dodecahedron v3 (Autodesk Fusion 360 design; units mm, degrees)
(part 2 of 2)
sketch "Sketch12" plane through (4.7433, 19.8444, -10.2039) normal (0.2079, 0.8699, -0.4473) x axis (-0.9726, 0.2325, 0)
  line L1 (-17.4918, 12.7643) -> (-28.5055, 46.2674)
  line L2 (17.775, 12.8859) -> (-17.4918, 12.7643)
  line L3 (28.5573, 46.4642) -> (17.775, 12.8859)
  line L4 (-0.0456, 67.0951) -> (28.5573, 46.4642)
  line L5 (-28.5055, 46.2674) -> (-0.0456, 67.0951)
  line L6 (-30.2958, 66.0429) -> (-30.2958, 36.2773)
  line L7 (-0.5302, 66.0429) -> (-30.2958, 66.0429)
  line L8 (29.2354, 66.0429) -> (-0.5302, 66.0429)
  line L9 (29.2354, 36.2773) -> (29.2354, 66.0429)
  line L10 (29.2354, 6.5116) -> (29.2354, 36.2773)
  line L11 (-0.5302, 6.5116) -> (29.2354, 6.5116)
  line L12 (-30.2958, 6.5116) -> (-0.5302, 6.5116)
  line L13 (-30.2958, 36.2773) -> (-30.2958, 6.5116)
  curve K1 (2.3724, 16.2406) -> (1.4713, 16.1226)
  curve K2 (1.9297, 17.1948) -> (2.3724, 16.2406)
  curve K3 (1.5053, 19.8254) -> (1.9297, 17.1948)
  curve K4 (2.1828, 21.6353) -> (1.5053, 19.8254)
  curve K5 (2.1525, 23.8138) -> (2.1828, 21.6353)
  curve K6 (1.4481, 26.0743) -> (2.1525, 23.8138)
  curve K7 (2.1376, 26.8386) -> (1.4481, 26.0743)
  curve K8 (2.842, 25.6825) -> (2.1376, 26.8386)
  curve K9 (4.016, 24.576) -> (2.842, 25.6825)
  curve K10 (5.1901, 24.2437) -> (4.016, 24.576)
  curve K11 (2.9753, 28.5266) -> (5.1901, 24.2437)
  curve K12 (1.9028, 32.4009) -> (2.9753, 28.5266)
  curve K13 (2.3455, 34.8221) -> (1.9028, 32.4009)
  curve K14 (7.0685, 30.1247) -> (2.3455, 34.8221)
  curve K15 (9.4636, 26.5383) -> (7.0685, 30.1247)
  curve K16 (9.0345, 29.9776) -> (9.4636, 26.5383)
  curve K17 (9.4117, 31.0677) -> (9.0345, 29.9776)
  curve K18 (11.0674, 29.1728) -> (9.4117, 31.0677)
  curve K19 (12.8737, 28.4823) -> (11.0674, 29.1728)
  curve K20 (13.0657, 29.1867) -> (12.8737, 28.4823)
  curve K21 (14.1127, 28.4823) -> (13.0657, 29.1867)
  curve K22 (15.3543, 27.7778) -> (14.1127, 28.4823)
  curve K23 (16.5462, 26.6038) -> (15.3543, 27.7778)
  curve K24 (17.8696, 26.1998) -> (16.5462, 26.6038)
  curve K25 (18.6915, 27.5937) -> (17.8696, 26.1998)
  curve K26 (18.3393, 28.2472) -> (18.6915, 27.5937)
  curve K27 (15.3117, 29.4154) -> (18.3393, 28.2472)
  curve K28 (14.2524, 30.8588) -> (15.3117, 29.4154)
  curve K29 (13.1149, 32.0044) -> (14.2524, 30.8588)
  curve K30 (10.4098, 33.4565) -> (13.1149, 32.0044)
  curve K31 (12.0271, 33.8756) -> (10.4098, 33.4565)
  curve K32 (13.9056, 34.6198) -> (12.0271, 33.8756)
  curve K33 (10.8666, 35.0982) -> (13.9056, 34.6198)
  curve K34 (5.2312, 35.8627) -> (10.8666, 35.0982)
  curve K35 (3.2252, 37.3577) -> (5.2312, 35.8627)
  curve K36 (4.0879, 38.3816) -> (3.2252, 37.3577)
  curve K37 (4.4969, 38.5608) -> (4.0879, 38.3816)
  curve K38 (5.2336, 39.5415) -> (4.4969, 38.5608)
  curve K39 (5.9267, 39.5704) -> (5.2336, 39.5415)
  curve K40 (6.337, 39.338) -> (5.9267, 39.5704)
  curve K41 (6.8041, 40.0356) -> (6.337, 39.338)
  curve K42 (7.8635, 39.9458) -> (6.8041, 40.0356)
  curve K43 (14.4524, 39.7014) -> (7.8635, 39.9458)
  curve K44 (10.9801, 41.2972) -> (14.4524, 39.7014)
  curve K45 (10.6247, 42.6488) -> (10.9801, 41.2972)
  curve K46 (14.0408, 44.5275) -> (10.6247, 42.6488)
  curve K47 (17.9594, 46.0928) -> (14.0408, 44.5275)
  curve K48 (18.5527, 47.5194) -> (17.9594, 46.0928)
  curve K49 (18.0683, 48.7509) -> (18.5527, 47.5194)
  curve K50 (16.959, 48.4944) -> (18.0683, 48.7509)
  curve K51 (12.9265, 45.6232) -> (16.959, 48.4944)
  curve K52 (13.0036, 46.3276) -> (12.9265, 45.6232)
  curve K53 (10.8231, 45.0957) -> (13.0036, 46.3276)
  curve K54 (8.8427, 44.5263) -> (10.8231, 45.0957)
  curve K55 (9.5697, 47.032) -> (8.8427, 44.5263)
  line L14 (9.8552, 48.6757) -> (9.5697, 47.032)
  line L15 (8.5792, 47.0819) -> (9.8552, 48.6757)
  curve K56 (6.8227, 43.8092) -> (8.5792, 47.0819)
  curve K57 (1.6025, 39.9211) -> (6.8227, 43.8092)
  curve K58 (1.3157, 40.4431) -> (1.6025, 39.9211)
  curve K59 (1.9027, 42.7422) -> (1.3157, 40.4431)
  curve K60 (2.923, 46.324) -> (1.9027, 42.7422)
  curve K61 (5.1032, 50.7889) -> (2.923, 46.324)
  curve K62 (3.2393, 49.3801) -> (5.1032, 50.7889)
  curve K63 (1.7257, 47.9713) -> (3.2393, 49.3801)
  curve K64 (1.595, 49.0279) -> (1.7257, 47.9713)
  curve K65 (1.3836, 50.7889) -> (1.595, 49.0279)
  curve K66 (1.7983, 51.3716) -> (1.3836, 50.7889)
  curve K67 (2.6765, 52.9894) -> (1.7983, 51.3716)
  curve K68 (1.6962, 52.6909) -> (2.6765, 52.9894)
  curve K69 (1.2872, 54.6199) -> (1.6962, 52.6909)
  curve K70 (1.9747, 57.2853) -> (1.2872, 54.6199)
  curve K71 (0.7286, 58.5376) -> (1.9747, 57.2853)
  curve K72 (-0.4879, 57.155) -> (0.7286, 58.5376)
  curve K73 (-0.0926, 54.7834) -> (-0.4879, 57.155)
  curve K74 (-0.8248, 53.257) -> (-0.0926, 54.7834)
  curve K75 (-1.2201, 52.3136) -> (-0.8248, 53.257)
  curve K76 (-0.6308, 49.2627) -> (-1.2201, 52.3136)
  line L16 (-0.3465, 47.7364) -> (-0.6308, 49.2627)
  line L17 (-1.7783, 49.2627) -> (-0.3465, 47.7364)
  curve K77 (-3.7183, 50.7889) -> (-1.7783, 49.2627)
  curve K78 (-1.564, 46.2415) -> (-3.7183, 50.7889)
  curve K79 (-0.4454, 42.1324) -> (-1.564, 46.2415)
  curve K80 (-0.7422, 39.5182) -> (-0.4454, 42.1324)
  curve K81 (-2.572, 40.4657) -> (-0.7422, 39.5182)
  curve K82 (-5.7396, 44.6757) -> (-2.572, 40.4657)
  curve K83 (-7.1446, 47.1095) -> (-5.7396, 44.6757)
  line L18 (-8.4843, 48.6757) -> (-7.1446, 47.1095)
  line L19 (-8.2707, 47.032) -> (-8.4843, 48.6757)
  curve K84 (-7.7352, 44.2143) -> (-8.2707, 47.032)
  curve K85 (-9.2125, 45.0434) -> (-7.7352, 44.2143)
  curve K86 (-11.7161, 46.3276) -> (-9.2125, 45.0434)
  curve K87 (-12.1858, 45.6232) -> (-11.7161, 46.3276)
  curve K88 (-12.6554, 46.0358) -> (-12.1858, 45.6232)
  curve K89 (-14.0195, 47.0135) -> (-12.6554, 46.0358)
  curve K90 (-15.6871, 48.5967) -> (-14.0195, 47.0135)
  line L20 (-15.9906, 49.6149) -> (-15.6871, 48.5967)
  line L21 (-16.4034, 48.6063) -> (-15.9906, 49.6149)
  curve K91 (-17.3186, 47.2872) -> (-16.4034, 48.6063)
  curve K92 (-16.7192, 46.0928) -> (-17.3186, 47.2872)
  curve K93 (-12.6554, 44.1799) -> (-16.7192, 46.0928)
  curve K94 (-13.3875, 43.7447) -> (-12.6554, 44.1799)
  curve K95 (-13.8294, 43.2751) -> (-13.3875, 43.7447)
  curve K96 (-12.0406, 42.7888) -> (-13.8294, 43.2751)
  curve K97 (-9.3681, 42.1011) -> (-12.0406, 42.7888)
  line L22 (-8.194, 41.4299) -> (-9.3681, 42.1011)
  line L23 (-9.274, 41.4133) -> (-8.194, 41.4299)
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extrude "Extrude12" cut sketch "Sketch12" against normal blind 15
sketch "Sketch13" plane through (0, 0, 0) normal (0, 0, -1) x axis (1, 0, 0)
  line L1 (22.7927, -19.5062) -> (-11.5082, -27.7049)
  line L2 (25.5949, 15.6494) -> (22.7927, -19.5062)
  line L3 (-6.9742, 29.1781) -> (25.5949, 15.6494)
  line L4 (-29.9052, 2.3837) -> (-6.9742, 29.1781)
  line L5 (-11.5082, -27.7049) -> (-29.9052, 2.3837)
  line L6 (-30.2602, 29.1349) -> (-30.2602, -0.6307)
  line L7 (-0.4946, 29.1349) -> (-30.2602, 29.1349)
  line L8 (29.271, 29.1349) -> (-0.4946, 29.1349)
  line L9 (29.271, -0.6307) -> (29.271, 29.1349)
  line L10 (29.271, -30.3964) -> (29.271, -0.6307)
  line L11 (-0.4946, -30.3964) -> (29.271, -30.3964)
  line L12 (-30.2602, -30.3964) -> (-0.4946, -30.3964)
  line L13 (-30.2602, -0.6307) -> (-30.2602, -30.3964)
  curve K1 (1.7636, -23.0503) -> (0.8315, -23.1723)
  curve K2 (1.3057, -22.0632) -> (1.7636, -23.0503)
  curve K3 (0.8668, -19.3422) -> (1.3057, -22.0632)
  curve K4 (1.5675, -17.47) -> (0.8668, -19.3422)
  curve K5 (1.5362, -15.2166) -> (1.5675, -17.47)
  curve K6 (0.8075, -12.8784) -> (1.5362, -15.2166)
  curve K7 (1.5207, -12.0877) -> (0.8075, -12.8784)
  curve K8 (2.2494, -13.2837) -> (1.5207, -12.0877)
  curve K9 (3.4638, -14.4282) -> (2.2494, -13.2837)
  curve K10 (4.6782, -14.7719) -> (3.4638, -14.4282)
  curve K11 (2.3873, -10.3417) -> (4.6782, -14.7719)
  curve K12 (1.2778, -6.3341) -> (2.3873, -10.3417)
  curve K13 (1.7358, -3.8297) -> (1.2778, -6.3341)
  curve K14 (6.6213, -8.6887) -> (1.7358, -3.8297)
  curve K15 (9.0987, -12.3984) -> (6.6213, -8.6887)
  curve K16 (8.6549, -8.8408) -> (9.0987, -12.3984)
  curve K17 (9.0451, -7.7132) -> (8.6549, -8.8408)
  curve K18 (10.7577, -9.6733) -> (9.0451, -7.7132)
  curve K19 (12.6261, -10.3876) -> (10.7577, -9.6733)
  curve K20 (12.8248, -9.6589) -> (12.6261, -10.3876)
  curve K21 (13.9078, -10.3876) -> (12.8248, -9.6589)
  curve K22 (15.1921, -11.1162) -> (13.9078, -10.3876)
  curve K23 (16.425, -12.3306) -> (15.1921, -11.1162)
  curve K24 (17.7939, -12.7485) -> (16.425, -12.3306)
  curve K25 (18.644, -11.3067) -> (17.7939, -12.7485)
  curve K26 (18.2797, -10.6307) -> (18.644, -11.3067)
  curve K27 (15.148, -9.4223) -> (18.2797, -10.6307)
  curve K28 (14.0522, -7.9293) -> (15.148, -9.4223)
  curve K29 (12.8756, -6.7443) -> (14.0522, -7.9293)
  curve K30 (10.0774, -5.2422) -> (12.8756, -6.7443)
  curve K31 (11.7504, -4.8087) -> (10.0774, -5.2422)
  curve K32 (13.6935, -4.0389) -> (11.7504, -4.8087)
  curve K33 (10.55, -3.5441) -> (13.6935, -4.0389)
  curve K34 (4.7208, -2.7532) -> (10.55, -3.5441)
  curve K35 (2.6457, -1.2068) -> (4.7208, -2.7532)
  curve K36 (3.5381, -0.1478) -> (2.6457, -1.2068)
  curve K37 (3.9612, 0.0376) -> (3.5381, -0.1478)
  curve K38 (4.7232, 1.0521) -> (3.9612, 0.0376)
  curve K39 (5.4402, 1.082) -> (4.7232, 1.0521)
  curve K40 (5.8646, 0.8415) -> (5.4402, 1.082)
  curve K41 (6.3478, 1.5632) -> (5.8646, 0.8415)
  curve K42 (7.4436, 1.4703) -> (6.3478, 1.5632)
  curve K43 (14.2592, 1.2174) -> (7.4436, 1.4703)
  curve K44 (10.6674, 2.8682) -> (14.2592, 1.2174)
  curve K45 (10.2998, 4.2662) -> (10.6674, 2.8682)
  curve K46 (13.8334, 6.2095) -> (10.2998, 4.2662)
  curve K47 (17.8867, 7.8287) -> (13.8334, 6.2095)
  curve K48 (18.5004, 9.3043) -> (17.8867, 7.8287)
  curve K49 (17.9994, 10.5782) -> (18.5004, 9.3043)
  curve K50 (16.852, 10.3129) -> (17.9994, 10.5782)
  curve K51 (12.6808, 7.3429) -> (16.852, 10.3129)
  curve K52 (12.7605, 8.0716) -> (12.6808, 7.3429)
  curve K53 (10.505, 6.7973) -> (12.7605, 8.0716)
  curve K54 (8.4565, 6.2083) -> (10.505, 6.7973)
  curve K55 (9.2085, 8.8002) -> (8.4565, 6.2083)
  line L14 (9.5038, 10.5004) -> (9.2085, 8.8002)
  line L15 (8.1839, 8.8518) -> (9.5038, 10.5004)
  curve K56 (6.367, 5.4666) -> (8.1839, 8.8518)
  curve K57 (0.9672, 1.4447) -> (6.367, 5.4666)
  curve K58 (0.6706, 1.9847) -> (0.9672, 1.4447)
  curve K59 (1.2778, 4.3628) -> (0.6706, 1.9847)
  curve K60 (2.3332, 8.0679) -> (1.2778, 4.3628)
  curve K61 (4.5884, 12.6863) -> (2.3332, 8.0679)
  curve K62 (2.6603, 11.229) -> (4.5884, 12.6863)
  curve K63 (1.0947, 9.7717) -> (2.6603, 11.229)
  curve K64 (0.9595, 10.8647) -> (1.0947, 9.7717)
  curve K65 (0.7409, 12.6863) -> (0.9595, 10.8647)
  curve K66 (1.1698, 13.289) -> (0.7409, 12.6863)
  curve K67 (2.0782, 14.9625) -> (1.1698, 13.289)
  curve K68 (1.0642, 14.6537) -> (2.0782, 14.9625)
  curve K69 (0.6412, 16.649) -> (1.0642, 14.6537)
  curve K70 (1.3522, 19.4061) -> (0.6412, 16.649)
  curve K71 (0.0633, 20.7015) -> (1.3522, 19.4061)
  curve K72 (-1.195, 19.2713) -> (0.0633, 20.7015)
  curve K73 (-0.7861, 16.8182) -> (-1.195, 19.2713)
  curve K74 (-1.5436, 15.2393) -> (-0.7861, 16.8182)
  curve K75 (-1.9525, 14.2635) -> (-1.5436, 15.2393)
  curve K76 (-1.3428, 11.1076) -> (-1.9525, 14.2635)
  line L16 (-1.0488, 9.5289) -> (-1.3428, 11.1076)
  line L17 (-2.5298, 11.1076) -> (-1.0488, 9.5289)
  curve K77 (-4.5366, 12.6863) -> (-2.5298, 11.1076)
  curve K78 (-2.3082, 7.9825) -> (-4.5366, 12.6863)
  curve K79 (-1.1511, 3.7321) -> (-2.3082, 7.9825)
  curve K80 (-1.4581, 1.0279) -> (-1.1511, 3.7321)
  curve K81 (-3.3509, 2.008) -> (-1.4581, 1.0279)
  curve K82 (-6.6274, 6.3628) -> (-3.3509, 2.008)
  curve K83 (-8.0807, 8.8804) -> (-6.6274, 6.3628)
  line L18 (-9.4665, 10.5004) -> (-8.0807, 8.8804)
  line L19 (-9.2455, 8.8002) -> (-9.4665, 10.5004)
  curve K84 (-8.6916, 5.8856) -> (-9.2455, 8.8002)
  curve K85 (-10.2197, 6.7432) -> (-8.6916, 5.8856)
  curve K86 (-12.8095, 8.0716) -> (-10.2197, 6.7432)
  curve K87 (-13.2952, 7.3429) -> (-12.8095, 8.0716)
  curve K88 (-13.781, 7.7697) -> (-13.2952, 7.3429)
  curve K89 (-15.1921, 8.781) -> (-13.781, 7.7697)
  curve K90 (-16.917, 10.4187) -> (-15.1921, 8.781)
  line L20 (-17.231, 11.4719) -> (-16.917, 10.4187)
  line L21 (-17.6579, 10.4287) -> (-17.231, 11.4719)
  curve K91 (-18.6046, 9.0641) -> (-17.6579, 10.4287)
  curve K92 (-17.9847, 7.8287) -> (-18.6046, 9.0641)
  curve K93 (-13.781, 5.85) -> (-17.9847, 7.8287)
  curve K94 (-14.5383, 5.3998) -> (-13.781, 5.85)
  curve K95 (-14.9954, 4.9141) -> (-14.5383, 5.3998)
  curve K96 (-13.1451, 4.4111) -> (-14.9954, 4.9141)
  curve K97 (-10.3807, 3.6997) -> (-13.1451, 4.4111)
  line L22 (-9.1662, 3.0054) -> (-10.3807, 3.6997)
  line L23 (-10.2833, 2.9882) -> (-9.1662, 3.0054)
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sketch "Sketch14" plane through (-15.5016, -13.2664, -10.2039) normal (-0.6795, -0.5815, -0.4473) x axis (0.6502, -0.7598, 0)
  line L1 (-17.4918, 12.7643) -> (-28.5055, 46.2674)
  line L2 (17.775, 12.8859) -> (-17.4918, 12.7643)
  line L3 (28.5573, 46.4642) -> (17.775, 12.8859)
  line L4 (-0.0456, 67.0951) -> (28.5573, 46.4642)
  line L5 (-28.5055, 46.2674) -> (-0.0456, 67.0951)
  line L6 (-30.2602, 66.7535) -> (-30.2602, 36.9879)
  line L7 (-0.4946, 66.7535) -> (-30.2602, 66.7535)
  line L8 (29.271, 66.7535) -> (-0.4946, 66.7535)
  line L9 (29.271, 36.9879) -> (29.271, 66.7535)
  line L10 (29.271, 7.2223) -> (29.271, 36.9879)
  line L11 (-0.4946, 7.2223) -> (29.271, 7.2223)
  line L12 (-30.2602, 7.2223) -> (-0.4946, 7.2223)
  line L13 (-30.2602, 36.9879) -> (-30.2602, 7.2223)
  curve K1 (2.5655, 17.0704) -> (1.716, 16.9592)
  curve K2 (2.1482, 17.9701) -> (2.5655, 17.0704)
  curve K3 (1.7481, 20.4502) -> (2.1482, 17.9701)
  curve K4 (2.3868, 22.1566) -> (1.7481, 20.4502)
  curve K5 (2.3582, 24.2104) -> (2.3868, 22.1566)
  curve K6 (1.6941, 26.3417) -> (2.3582, 24.2104)
  curve K7 (2.3441, 27.0623) -> (1.6941, 26.3417)
  curve K8 (3.0083, 25.9722) -> (2.3441, 27.0623)
  curve K9 (4.1152, 24.9291) -> (3.0083, 25.9722)
  curve K10 (5.2221, 24.6158) -> (4.1152, 24.9291)
  curve K11 (3.134, 28.6537) -> (5.2221, 24.6158)
  curve K12 (2.1228, 32.3064) -> (3.134, 28.6537)
  curve K13 (2.5402, 34.5891) -> (2.1228, 32.3064)
  curve K14 (6.9931, 30.1604) -> (2.5402, 34.5891)
  curve K15 (9.2511, 26.7791) -> (6.9931, 30.1604)
  curve K16 (8.8466, 30.0218) -> (9.2511, 26.7791)
  curve K17 (9.2023, 31.0495) -> (8.8466, 30.0218)
  curve K18 (10.7633, 29.2629) -> (9.2023, 31.0495)
  curve K19 (12.4662, 28.6119) -> (10.7633, 29.2629)
  curve K20 (12.6473, 29.276) -> (12.4662, 28.6119)
  curve K21 (13.6344, 28.6119) -> (12.6473, 29.276)
  curve K22 (14.805, 27.9478) -> (13.6344, 28.6119)
  curve K23 (15.9287, 26.8409) -> (14.805, 27.9478)
  curve K24 (17.1764, 26.46) -> (15.9287, 26.8409)
  curve K25 (17.9512, 27.7742) -> (17.1764, 26.46)
  curve K26 (17.6192, 28.3903) -> (17.9512, 27.7742)
  curve K27 (14.7648, 29.4917) -> (17.6192, 28.3903)
  curve K28 (13.766, 30.8525) -> (14.7648, 29.4917)
  curve K29 (12.6936, 31.9326) -> (13.766, 30.8525)
  curve K30 (10.1432, 33.3016) -> (12.6936, 31.9326)
  curve K31 (11.668, 33.6968) -> (10.1432, 33.3016)
  curve K32 (13.4391, 34.3984) -> (11.668, 33.6968)
  curve K33 (10.5739, 34.8495) -> (13.4391, 34.3984)
  curve K34 (5.2608, 35.5702) -> (10.5739, 34.8495)
  curve K35 (3.3695, 36.9797) -> (5.2608, 35.5702)
  curve K36 (4.1829, 37.945) -> (3.3695, 36.9797)
  curve K37 (4.5685, 38.114) -> (4.1829, 37.945)
  curve K38 (5.2631, 39.0386) -> (4.5685, 38.114)
  curve K39 (5.9166, 39.0659) -> (5.2631, 39.0386)
  curve K40 (6.3034, 38.8467) -> (5.9166, 39.0659)
  curve K41 (6.7438, 39.5044) -> (6.3034, 38.8467)
  curve K42 (7.7426, 39.4198) -> (6.7438, 39.5044)
  curve K43 (13.9546, 39.1893) -> (7.7426, 39.4198)
  curve K44 (10.6809, 40.6939) -> (13.9546, 39.1893)
  curve K45 (10.3459, 41.9681) -> (10.6809, 40.6939)
  curve K46 (13.5666, 43.7394) -> (10.3459, 41.9681)
  curve K47 (17.261, 45.2152) -> (13.5666, 43.7394)
  curve K48 (17.8203, 46.5602) -> (17.261, 45.2152)
  curve K49 (17.3637, 47.7213) -> (17.8203, 46.5602)
  curve K50 (16.3179, 47.4794) -> (17.3637, 47.7213)
  curve K51 (12.516, 44.7724) -> (16.3179, 47.4794)
  curve K52 (12.5887, 45.4366) -> (12.516, 44.7724)
  curve K53 (10.5329, 44.2751) -> (12.5887, 45.4366)
  curve K54 (8.6658, 43.7383) -> (10.5329, 44.2751)
  curve K55 (9.3512, 46.1007) -> (8.6658, 43.7383)
  line L14 (9.6203, 47.6503) -> (9.3512, 46.1007)
  line L15 (8.4174, 46.1477) -> (9.6203, 47.6503)
  curve K56 (6.7613, 43.0622) -> (8.4174, 46.1477)
  curve K57 (1.8397, 39.3965) -> (6.7613, 43.0622)
  curve K58 (1.5693, 39.8887) -> (1.8397, 39.3965)
  curve K59 (2.1227, 42.0562) -> (1.5693, 39.8887)
  curve K60 (3.0847, 45.4332) -> (2.1227, 42.0562)
  curve K61 (5.1402, 49.6427) -> (3.0847, 45.4332)
  curve K62 (3.3829, 48.3145) -> (5.1402, 49.6427)
  curve K63 (1.9558, 46.9862) -> (3.3829, 48.3145)
  curve K64 (1.8326, 47.9824) -> (1.9558, 46.9862)
  curve K65 (1.6333, 49.6427) -> (1.8326, 47.9824)
  curve K66 (2.0243, 50.1921) -> (1.6333, 49.6427)
  curve K67 (2.8522, 51.7173) -> (2.0243, 50.1921)
  curve K68 (1.928, 51.4359) -> (2.8522, 51.7173)
  curve K69 (1.5425, 53.2545) -> (1.928, 51.4359)
  curve K70 (2.1906, 55.7675) -> (1.5425, 53.2545)
  curve K71 (1.0158, 56.9482) -> (2.1906, 55.7675)
  curve K72 (-0.1311, 55.6446) -> (1.0158, 56.9482)
  curve K73 (0.2416, 53.4087) -> (-0.1311, 55.6446)
  curve K74 (-0.4488, 51.9696) -> (0.2416, 53.4087)
  curve K75 (-0.8215, 51.0802) -> (-0.4488, 51.9696)
  curve K76 (-0.2658, 48.2038) -> (-0.8215, 51.0802)
  line L16 (0.0022, 46.7648) -> (-0.2658, 48.2038)
  line L17 (-1.3478, 48.2038) -> (0.0022, 46.7648)
  curve K77 (-3.1768, 49.6427) -> (-1.3478, 48.2038)
  curve K78 (-1.1457, 45.3554) -> (-3.1768, 49.6427)
  curve K79 (-0.0911, 41.4813) -> (-1.1457, 45.3554)
  curve K80 (-0.3709, 39.0166) -> (-0.0911, 41.4813)
  curve K81 (-2.0961, 39.9099) -> (-0.3709, 39.0166)
  curve K82 (-5.0825, 43.8791) -> (-2.0961, 39.9099)
  curve K83 (-6.4071, 46.1737) -> (-5.0825, 43.8791)
  line L18 (-7.6702, 47.6503) -> (-6.4071, 46.1737)
  line L19 (-7.4688, 46.1007) -> (-7.6702, 47.6503)
  curve K84 (-6.9639, 43.4442) -> (-7.4688, 46.1007)
  curve K85 (-8.3567, 44.2258) -> (-6.9639, 43.4442)
  curve K86 (-10.7172, 45.4365) -> (-8.3567, 44.2258)
  curve K87 (-11.1599, 44.7724) -> (-10.7172, 45.4365)
  curve K88 (-11.6027, 45.1615) -> (-11.1599, 44.7724)
  curve K89 (-12.8888, 46.0832) -> (-11.6027, 45.1615)
  curve K90 (-14.461, 47.5759) -> (-12.8888, 46.0832)
  line L20 (-14.7472, 48.5358) -> (-14.461, 47.5759)
  line L21 (-15.1363, 47.5849) -> (-14.7472, 48.5358)
  curve K91 (-15.9992, 46.3412) -> (-15.1363, 47.5849)
  curve K92 (-15.4341, 45.2152) -> (-15.9992, 46.3412)
  curve K93 (-11.6027, 43.4117) -> (-15.4341, 45.2152)
  curve K94 (-12.2929, 43.0014) -> (-11.6027, 43.4117)
  curve K95 (-12.7096, 42.5586) -> (-12.2929, 43.0014)
  curve K96 (-11.0231, 42.1002) -> (-12.7096, 42.5586)
  curve K97 (-8.5034, 41.4518) -> (-11.0231, 42.1002)
  line L22 (-7.3965, 40.819) -> (-8.5034, 41.4518)
  line L23 (-8.4147, 40.8033) -> (-7.3965, 40.819)
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extrude "Extrude14" cut sketch "Sketch14" against normal blind 15
sketch "Sketch15" plane through (-17.4074, 10.6434, -10.2039) normal (-0.7631, 0.4666, -0.4473) x axis (-0.5216, -0.8532, 0)
  line L1 (-17.4918, 12.7643) -> (-28.5055, 46.2674)
  line L2 (17.775, 12.8859) -> (-17.4918, 12.7643)
  line L3 (28.5573, 46.4642) -> (17.775, 12.8859)
  line L4 (-0.0456, 67.0951) -> (28.5573, 46.4642)
  line L5 (-28.5055, 46.2674) -> (-0.0456, 67.0951)
  line L6 (-29.498, 68.694) -> (-29.498, 38.9283)
  line L7 (0.2676, 68.694) -> (-29.498, 68.694)
  line L8 (30.0333, 68.694) -> (0.2676, 68.694)
  line L9 (30.0333, 38.9283) -> (30.0333, 68.694)
  line L10 (30.0333, 9.1627) -> (30.0333, 38.9283)
  line L11 (0.2676, 9.1627) -> (30.0333, 9.1627)
  line L12 (-29.498, 9.1627) -> (0.2676, 9.1627)
  line L13 (-29.498, 38.9283) -> (-29.498, 9.1627)
  curve K1 (3.5236, 18.0358) -> (2.6323, 17.9191)
  curve K2 (3.0858, 18.9796) -> (3.5236, 18.0358)
  curve K3 (2.666, 21.5815) -> (3.0858, 18.9796)
  curve K4 (3.3361, 23.3716) -> (2.666, 21.5815)
  curve K5 (3.3061, 25.5263) -> (3.3361, 23.3716)
  curve K6 (2.6094, 27.7621) -> (3.3061, 25.5263)
  curve K7 (3.2913, 28.5181) -> (2.6094, 27.7621)
  curve K8 (3.9881, 27.3746) -> (3.2913, 28.5181)
  curve K9 (5.1493, 26.2802) -> (3.9881, 27.3746)
  curve K10 (6.3105, 25.9515) -> (5.1493, 26.2802)
  curve K11 (4.1199, 30.1877) -> (6.3105, 25.9515)
  curve K12 (3.0591, 34.0197) -> (4.1199, 30.1877)
  curve K13 (3.497, 36.4144) -> (3.0591, 34.0197)
  curve K14 (8.1685, 31.7683) -> (3.497, 36.4144)
  curve K15 (10.5374, 28.2211) -> (8.1685, 31.7683)
  curve K16 (10.113, 31.6229) -> (10.5374, 28.2211)
  curve K17 (10.4861, 32.7011) -> (10.113, 31.6229)
  curve K18 (12.1237, 30.8268) -> (10.4861, 32.7011)
  curve K19 (13.9103, 30.1438) -> (12.1237, 30.8268)
  curve K20 (14.1002, 30.8406) -> (13.9103, 30.1438)
  curve K21 (15.1358, 30.1438) -> (14.1002, 30.8406)
  curve K22 (16.3638, 29.4471) -> (15.1358, 30.1438)
  curve K23 (17.5427, 28.2859) -> (16.3638, 29.4471)
  curve K24 (18.8517, 27.8863) -> (17.5427, 28.2859)
  curve K25 (19.6645, 29.265) -> (18.8517, 27.8863)
  curve K26 (19.3162, 29.9113) -> (19.6645, 29.265)
  curve K27 (16.3217, 31.0668) -> (19.3162, 29.9113)
  curve K28 (15.2739, 32.4944) -> (16.3217, 31.0668)
  curve K29 (14.1489, 33.6275) -> (15.2739, 32.4944)
  curve K30 (11.4732, 35.0638) -> (14.1489, 33.6275)
  curve K31 (13.0729, 35.4783) -> (11.4732, 35.0638)
  curve K32 (14.9309, 36.2144) -> (13.0729, 35.4783)
  curve K33 (11.9251, 36.6876) -> (14.9309, 36.2144)
  curve K34 (6.3512, 37.4437) -> (11.9251, 36.6876)
  curve K35 (4.3671, 38.9224) -> (6.3512, 37.4437)
  curve K36 (5.2204, 39.9351) -> (4.3671, 38.9224)
  curve K37 (5.6249, 40.1124) -> (5.2204, 39.9351)
  curve K38 (6.3535, 41.0824) -> (5.6249, 40.1124)
  curve K39 (7.0391, 41.111) -> (6.3535, 41.0824)
  curve K40 (7.4449, 40.8811) -> (7.0391, 41.111)
  curve K41 (7.907, 41.5711) -> (7.4449, 40.8811)
  curve K42 (8.9547, 41.4823) -> (7.907, 41.5711)
  curve K43 (15.4718, 41.2405) -> (8.9547, 41.4823)
  curve K44 (12.0373, 42.8189) -> (15.4718, 41.2405)
  curve K45 (11.6858, 44.1557) -> (12.0373, 42.8189)
  curve K46 (15.0647, 46.0139) -> (11.6858, 44.1557)
  curve K47 (18.9405, 47.5622) -> (15.0647, 46.0139)
  curve K48 (19.5272, 48.9732) -> (18.9405, 47.5622)
  curve K49 (19.0482, 50.1913) -> (19.5272, 48.9732)
  curve K50 (17.951, 49.9376) -> (19.0482, 50.1913)
  curve K51 (13.9625, 47.0977) -> (17.951, 49.9376)
  curve K52 (14.0388, 47.7944) -> (13.9625, 47.0977)
  curve K53 (11.882, 46.576) -> (14.0388, 47.7944)
  curve K54 (9.9233, 46.0128) -> (11.882, 46.576)
  curve K55 (10.6423, 48.4911) -> (9.9233, 46.0128)
  line L14 (10.9247, 50.1168) -> (10.6423, 48.4911)
  line L15 (9.6627, 48.5404) -> (10.9247, 50.1168)
  curve K56 (7.9253, 45.3035) -> (9.6627, 48.5404)
  curve K57 (2.7621, 41.4578) -> (7.9253, 45.3035)
  curve K58 (2.4784, 41.9742) -> (2.7621, 41.4578)
  curve K59 (3.059, 44.2481) -> (2.4784, 41.9742)
  curve K60 (4.0682, 47.7909) -> (3.059, 44.2481)
  curve K61 (6.2246, 52.207) -> (4.0682, 47.7909)
  curve K62 (4.381, 50.8136) -> (6.2246, 52.207)
  curve K63 (2.8839, 49.4201) -> (4.381, 50.8136)
  curve K64 (2.7546, 50.4652) -> (2.8839, 49.4201)
  curve K65 (2.5456, 52.207) -> (2.7546, 50.4652)
  curve K66 (2.9558, 52.7833) -> (2.5456, 52.207)
  curve K67 (3.8243, 54.3835) -> (2.9558, 52.7833)
  curve K68 (2.8548, 54.0883) -> (3.8243, 54.3835)
  curve K69 (2.4503, 55.9961) -> (2.8548, 54.0883)
  curve K70 (3.1302, 58.6325) -> (2.4503, 55.9961)
  curve K71 (1.8978, 59.8711) -> (3.1302, 58.6325)
  curve K72 (0.6946, 58.5036) -> (1.8978, 59.8711)
  curve K73 (1.0855, 56.1579) -> (0.6946, 58.5036)
  curve K74 (0.3613, 54.6482) -> (1.0855, 56.1579)
  curve K75 (-0.0297, 53.7151) -> (0.3613, 54.6482)
  curve K76 (0.5532, 50.6975) -> (-0.0297, 53.7151)
  line L16 (0.8344, 49.1879) -> (0.5532, 50.6975)
  line L17 (-0.5818, 50.6975) -> (0.8344, 49.1879)
  curve K77 (-2.5006, 52.207) -> (-0.5818, 50.6975)
  curve K78 (-0.3698, 47.7093) -> (-2.5006, 52.207)
  curve K79 (0.7366, 43.645) -> (-0.3698, 47.7093)
  curve K80 (0.443, 41.0593) -> (0.7366, 43.645)
  curve K81 (-1.3669, 41.9965) -> (0.443, 41.0593)
  curve K82 (-4.4999, 46.1605) -> (-1.3669, 41.9965)
  curve K83 (-5.8896, 48.5678) -> (-4.4999, 46.1605)
  line L18 (-7.2146, 50.1168) -> (-5.8896, 48.5678)
  line L19 (-7.0034, 48.4911) -> (-7.2146, 50.1168)
  curve K84 (-6.4737, 45.7042) -> (-7.0034, 48.4911)
  curve K85 (-7.9348, 46.5242) -> (-6.4737, 45.7042)
  curve K86 (-10.4112, 47.7944) -> (-7.9348, 46.5242)
  curve K87 (-10.8757, 47.0977) -> (-10.4112, 47.7944)
  curve K88 (-11.3401, 47.5058) -> (-10.8757, 47.0977)
  curve K89 (-12.6894, 48.4728) -> (-11.3401, 47.5058)
  curve K90 (-14.3388, 50.0387) -> (-12.6894, 48.4728)
  line L20 (-14.639, 51.0458) -> (-14.3388, 50.0387)
  line L21 (-15.0472, 50.0482) -> (-14.639, 51.0458)
  curve K91 (-15.9525, 48.7435) -> (-15.0472, 50.0482)
  curve K92 (-15.3597, 47.5621) -> (-15.9525, 48.7435)
  curve K93 (-11.3402, 45.6702) -> (-15.3597, 47.5621)
  curve K94 (-12.0643, 45.2397) -> (-11.3402, 45.6702)
  curve K95 (-12.5014, 44.7752) -> (-12.0643, 45.2397)
  curve K96 (-10.7321, 44.2943) -> (-12.5014, 44.7752)
  curve K97 (-8.0887, 43.614) -> (-10.7321, 44.2943)
  line L22 (-6.9275, 42.9502) -> (-8.0887, 43.614)
  line L23 (-7.9957, 42.9337) -> (-6.9275, 42.9502)
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extrude "Extrude15" cut sketch "Sketch15" against normal blind 10
sketch "Sketch16" plane through (-21.6865, 50.0122, 27.2617) normal (-0.3558, 0.8206, 0.4473) x axis (-0.9175, -0.3978, 0)
  line L1 (17.1308, 61.4393) -> (28.1445, 27.9362)
  line L2 (-18.136, 61.3177) -> (17.1308, 61.4393)
  line L3 (-28.9184, 27.7394) -> (-18.136, 61.3177)
  line L4 (-0.3154, 7.1085) -> (-28.9184, 27.7394)
  line L5 (28.1445, 27.9362) -> (-0.3154, 7.1085)
  line L6 (-29.8702, 70.3016) -> (-29.8702, 40.536)
  line L7 (-0.1046, 70.3016) -> (-29.8702, 70.3016)
  line L8 (29.661, 70.3016) -> (-0.1046, 70.3016)
  line L9 (29.661, 40.536) -> (29.661, 70.3016)
  line L10 (29.661, 10.7703) -> (29.661, 40.536)
  line L11 (-0.1046, 10.7703) -> (29.661, 10.7703)
  line L12 (-29.8702, 10.7703) -> (-0.1046, 10.7703)
  line L13 (-29.8702, 40.536) -> (-29.8702, 10.7703)
  curve K1 (2.6218, 19.1111) -> (1.7464, 18.9965)
  curve K2 (2.1918, 20.0382) -> (2.6218, 19.1111)
  curve K3 (1.7795, 22.5939) -> (2.1918, 20.0382)
  curve K4 (2.4376, 24.3523) -> (1.7795, 22.5939)
  curve K5 (2.4082, 26.4688) -> (2.4376, 24.3523)
  curve K6 (1.7238, 28.6651) -> (2.4082, 26.4688)
  curve K7 (2.3937, 29.4077) -> (1.7238, 28.6651)
  curve K8 (3.0781, 28.2844) -> (2.3937, 29.4077)
  curve K9 (4.2187, 27.2094) -> (3.0781, 28.2844)
  curve K10 (5.3594, 26.8865) -> (4.2187, 27.2094)
  curve K11 (3.2076, 31.0476) -> (5.3594, 26.8865)
  curve K12 (2.1656, 34.8117) -> (3.2076, 31.0476)
  curve K13 (2.5957, 37.164) -> (2.1656, 34.8117)
  curve K14 (7.1844, 32.6002) -> (2.5957, 37.164)
  curve K15 (9.5113, 29.1159) -> (7.1844, 32.6002)
  curve K16 (9.0945, 32.4574) -> (9.5113, 29.1159)
  curve K17 (9.461, 33.5165) -> (9.0945, 32.4574)
  curve K18 (11.0696, 31.6754) -> (9.461, 33.5165)
  curve K19 (12.8245, 31.0046) -> (11.0696, 31.6754)
  curve K20 (13.0111, 31.6889) -> (12.8245, 31.0046)
  curve K21 (14.0283, 31.0046) -> (13.0111, 31.6889)
  curve K22 (15.2345, 30.3202) -> (14.0283, 31.0046)
  curve K23 (16.3926, 29.1795) -> (15.2345, 30.3202)
  curve K24 (17.6783, 28.787) -> (16.3926, 29.1795)
  curve K25 (18.4768, 30.1413) -> (17.6783, 28.787)
  curve K26 (18.1346, 30.7761) -> (18.4768, 30.1413)
  curve K27 (15.1931, 31.9112) -> (18.1346, 30.7761)
  curve K28 (14.1639, 33.3135) -> (15.1931, 31.9112)
  curve K29 (13.0588, 34.4265) -> (14.1639, 33.3135)
  curve K30 (10.4306, 35.8373) -> (13.0588, 34.4265)
  curve K31 (12.002, 36.2445) -> (10.4306, 35.8373)
  curve K32 (13.827, 36.9675) -> (12.002, 36.2445)
  curve K33 (10.8744, 37.4323) -> (13.827, 36.9675)
  curve K34 (5.3993, 38.1751) -> (10.8744, 37.4323)
  curve K35 (3.4504, 39.6276) -> (5.3993, 38.1751)
  curve K36 (4.2886, 40.6223) -> (3.4504, 39.6276)
  curve K37 (4.6859, 40.7964) -> (4.2886, 40.6223)
  curve K38 (5.4016, 41.7492) -> (4.6859, 40.7964)
  curve K39 (6.0751, 41.7773) -> (5.4016, 41.7492)
  curve K40 (6.4737, 41.5515) -> (6.0751, 41.7773)
  curve K41 (6.9275, 42.2293) -> (6.4737, 41.5515)
  curve K42 (7.9567, 42.1421) -> (6.9275, 42.2293)
  curve K43 (14.3583, 41.9046) -> (7.9567, 42.1421)
  curve K44 (10.9847, 43.455) -> (14.3583, 41.9046)
  curve K45 (10.6394, 44.7681) -> (10.9847, 43.455)
  curve K46 (13.9584, 46.5934) -> (10.6394, 44.7681)
  curve K47 (17.7655, 48.1142) -> (13.9584, 46.5934)
  curve K48 (18.3419, 49.5002) -> (17.7655, 48.1142)
  curve K49 (17.8713, 50.6967) -> (18.3419, 49.5002)
  curve K50 (16.7936, 50.4475) -> (17.8713, 50.6967)
  curve K51 (12.8758, 47.6579) -> (16.7936, 50.4475)
  curve K52 (12.9507, 48.3423) -> (12.8758, 47.6579)
  curve K53 (10.8322, 47.1455) -> (12.9507, 48.3423)
  curve K54 (8.9081, 46.5923) -> (10.8322, 47.1455)
  curve K55 (9.6145, 49.0267) -> (8.9081, 46.5923)
  line L14 (9.8918, 50.6236) -> (9.6145, 49.0267)
  line L15 (8.6521, 49.0751) -> (9.8918, 50.6236)
  curve K56 (6.9456, 45.8956) -> (8.6521, 49.0751)
  curve K57 (1.8738, 42.118) -> (6.9456, 45.8956)
  curve K58 (1.5952, 42.6252) -> (1.8738, 42.118)
  curve K59 (2.1655, 44.8589) -> (1.5952, 42.6252)
  curve K60 (3.1568, 48.3388) -> (2.1655, 44.8589)
  curve K61 (5.275, 52.6768) -> (3.1568, 48.3388)
  curve K62 (3.4641, 51.308) -> (5.275, 52.6768)
  curve K63 (1.9935, 49.9392) -> (3.4641, 51.308)
  curve K64 (1.8665, 50.9658) -> (1.9935, 49.9392)
  curve K65 (1.6612, 52.6768) -> (1.8665, 50.9658)
  curve K66 (2.0641, 53.2429) -> (1.6612, 52.6768)
  curve K67 (2.9173, 54.8146) -> (2.0641, 53.2429)
  curve K68 (1.9649, 54.5246) -> (2.9173, 54.8146)
  curve K69 (1.5676, 56.3987) -> (1.9649, 54.5246)
  curve K70 (2.2355, 58.9883) -> (1.5676, 56.3987)
  curve K71 (1.0248, 60.205) -> (2.2355, 58.9883)
  curve K72 (-0.1571, 58.8617) -> (1.0248, 60.205)
  curve K73 (0.227, 56.5576) -> (-0.1571, 58.8617)
  curve K74 (-0.4844, 55.0747) -> (0.227, 56.5576)
  curve K75 (-0.8685, 54.1581) -> (-0.4844, 55.0747)
  curve K76 (-0.2959, 51.1939) -> (-0.8685, 54.1581)
  line L16 (-0.0197, 49.7111) -> (-0.2959, 51.1939)
  line L17 (-1.4108, 51.1939) -> (-0.0197, 49.7111)
  curve K77 (-3.2956, 52.6768) -> (-1.4108, 51.1939)
  curve K78 (-1.2026, 48.2587) -> (-3.2956, 52.6768)
  curve K79 (-0.1158, 44.2664) -> (-1.2026, 48.2587)
  curve K80 (-0.4041, 41.7266) -> (-0.1158, 44.2664)
  curve K81 (-2.1819, 42.6471) -> (-0.4041, 41.7266)
  curve K82 (-5.2595, 46.7374) -> (-2.1819, 42.6471)
  curve K83 (-6.6245, 49.102) -> (-5.2595, 46.7374)
  line L18 (-7.926, 50.6236) -> (-6.6245, 49.102)
  line L19 (-7.7185, 49.0267) -> (-7.926, 50.6236)
  curve K84 (-7.1982, 46.2891) -> (-7.7185, 49.0267)
  curve K85 (-8.6335, 47.0947) -> (-7.1982, 46.2891)
  curve K86 (-11.066, 48.3423) -> (-8.6335, 47.0947)
  curve K87 (-11.5222, 47.6579) -> (-11.066, 48.3423)
  curve K88 (-11.9785, 48.0588) -> (-11.5222, 47.6579)
  curve K89 (-13.3038, 49.0087) -> (-11.9785, 48.0588)
  curve K90 (-14.924, 50.5469) -> (-13.3038, 49.0087)
  line L20 (-15.2189, 51.5361) -> (-14.924, 50.5469)
  line L21 (-15.6199, 50.5562) -> (-15.2189, 51.5361)
  curve K91 (-16.5091, 49.2746) -> (-15.6199, 50.5562)
  curve K92 (-15.9268, 48.1142) -> (-16.5091, 49.2746)
  curve K93 (-11.9785, 46.2557) -> (-15.9268, 48.1142)
  curve K94 (-12.6898, 45.8329) -> (-11.9785, 46.2557)
  curve K95 (-13.1191, 45.3766) -> (-12.6898, 45.8329)
  curve K96 (-11.3812, 44.9042) -> (-13.1191, 45.3766)
  curve K97 (-8.7847, 44.236) -> (-11.3812, 44.9042)
  line L22 (-7.644, 43.5839) -> (-8.7847, 44.236)
  line L23 (-8.6933, 43.5678) -> (-7.644, 43.5839)
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extrude "Extrude16" cut sketch "Sketch16" against normal blind 5
sketch "Sketch17" plane through (0, 0, 0) normal (0, 0, -1) x axis (1, 0, 0)
  line L1 (22.7927, -19.5062) -> (-11.5082, -27.7049)
  line L2 (25.5949, 15.6494) -> (22.7927, -19.5062)
  line L3 (-6.9742, 29.1781) -> (25.5949, 15.6494)
  line L4 (-29.9052, 2.3837) -> (-6.9742, 29.1781)
  line L5 (-11.5082, -27.7049) -> (-29.9052, 2.3837)
  circle C1 centre (0, 0) radius 40
  point P1 (0, 0)
  point P7 (0, 0)
  coincident P1 P7
  dimension "d39" diameter C1 = 80
extrude "Extrude17" new body sketch "Sketch17" along normal blind 20
sketch "Sketch18" plane through (0, 0, 2) normal (0, 0, 1) x axis (-1, 0, 0)
  line L1 (11.5082, -27.7049) -> (-22.7927, -19.5062)
  line L2 (29.9052, 2.3837) -> (11.5082, -27.7049)
  line L3 (6.9742, 29.1781) -> (29.9052, 2.3837)
  line L4 (-25.5949, 15.6494) -> (6.9742, 29.1781)
  line L5 (-22.7927, -19.5062) -> (-25.5949, 15.6494)
  circle C1 centre (0, 0) radius 8.0623
  circle C2 centre (0, 0) radius 11.0623
  point P1 (0, 0)
  point P7 (0, 0)
  coincident P1 P7
  dimension "d42" = 3
extrude "Extrude18" new body sketch "Sketch18" profile of C1 C2 along normal blind 50
work_plane "WorkPlane3" RotateAngle 0
sketch "Sketch19" plane through (40, 0, 0) normal (1, 0, 0) x axis (0, 1, 0)
  circle C1 centre (-15, -10) radius 7.5
  circle C2 centre (15, -10) radius 7.5
  dimension "d46" diameter C1 = 15
  dimension "d47" diameter C2 = 15
extrude "Extrude19" new body sketch "Sketch19" along normal blind 5
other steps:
base_feature "Base Feature"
